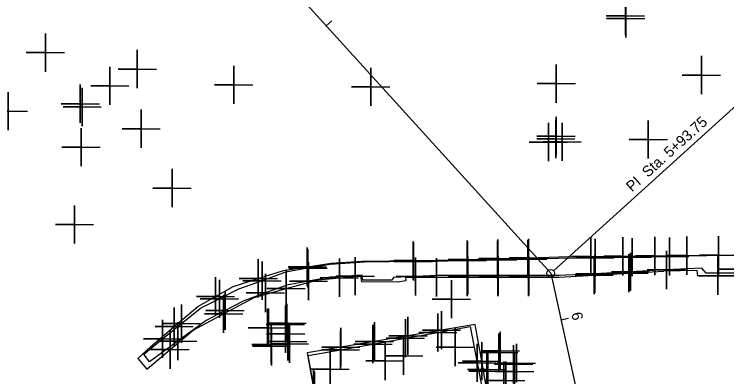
# Model space of a CAD drawing. Extents: x 2260968 to 2264340, y 653057 to 655850.
# Drawn here: x 2261593.4 to 2261686.7, y 655174 to 655221.5 of the extents above; entities that cross this region are included whole.
import ezdxf

# ---------------------------------------------------------------- set-up
doc = ezdxf.new("R2010")
doc.units = 0
for name, color, linetype in [('CL_X_Construction', 7, 'Continuous'), ('Default', 7, 'Continuous'), ('GE_X_CL_10', 7, 'Continuous')]:
    doc.layers.add(name, color=color, linetype=linetype)

msp = doc.modelspace()

# ---------------------------------------------------------------- linework, layer by layer
at = {"layer": 'CL_X_Construction'}
for p, q in [((2261565.655, 655295.67), (2261663.661, 655187.525)), ((2261565.655, 655295.67), (2261663.661, 655187.525)), ((2261663.661, 655187.525), (2261687.579, 655078.757)), ((2261663.661, 655187.525), (2261687.579, 655078.757))]:
    msp.add_line(p, q, dxfattribs=at)
at = {"layer": 'Default'}
for points in [[(2261673.434, 655221.244), (2261673.434, 655223.744), (2261673.434, 655221.244), (2261670.934, 655221.244), (2261673.434, 655221.244), (2261673.434, 655218.744), (2261673.434, 655221.244), (2261675.934, 655221.244)], [(2261673.483, 655220.911), (2261673.483, 655223.411), (2261673.483, 655220.911), (2261670.983, 655220.911), (2261673.483, 655220.911), (2261673.483, 655218.411), (2261673.483, 655220.911), (2261675.983, 655220.911)], [(2261597.529, 655216.43), (2261597.529, 655218.93), (2261597.529, 655216.43), (2261595.029, 655216.43), (2261597.529, 655216.43), (2261597.529, 655213.93), (2261597.529, 655216.43), (2261600.029, 655216.43)], [(2261609.557, 655214.277), (2261609.557, 655216.777), (2261609.557, 655214.277), (2261607.057, 655214.277), (2261609.557, 655214.277), (2261609.557, 655211.777), (2261609.557, 655214.277), (2261612.057, 655214.277)], [(2261683.387, 655213.501), (2261683.387, 655216.001), (2261683.387, 655213.501), (2261680.887, 655213.501), (2261683.387, 655213.501), (2261683.387, 655211.001), (2261683.387, 655213.501), (2261685.887, 655213.501)], [(2261605.963, 655212.074), (2261605.963, 655214.574), (2261605.963, 655212.074), (2261603.463, 655212.074), (2261605.963, 655212.074), (2261605.963, 655209.574), (2261605.963, 655212.074), (2261608.463, 655212.074)], [(2261622.179, 655212.221), (2261622.179, 655214.721), (2261622.179, 655212.221), (2261619.679, 655212.221), (2261622.179, 655212.221), (2261622.179, 655209.721), (2261622.179, 655212.221), (2261624.679, 655212.221)], [(2261664.389, 655212.376), (2261664.389, 655214.876), (2261664.389, 655212.376), (2261661.889, 655212.376), (2261664.389, 655212.376), (2261664.389, 655209.876), (2261664.389, 655212.376), (2261666.889, 655212.376)], [(2261640.108, 655211.946), (2261640.108, 655214.446), (2261640.108, 655211.946), (2261637.608, 655211.946), (2261640.108, 655211.946), (2261640.108, 655209.446), (2261640.108, 655211.946), (2261642.608, 655211.946)], [(2261602.088, 655209.738), (2261602.088, 655212.238), (2261602.088, 655209.738), (2261599.588, 655209.738), (2261602.088, 655209.738), (2261602.088, 655207.238), (2261602.088, 655209.738), (2261604.588, 655209.738)], [(2261602.333, 655209.312), (2261602.333, 655211.812), (2261602.333, 655209.312), (2261599.833, 655209.312), (2261602.333, 655209.312), (2261602.333, 655206.812), (2261602.333, 655209.312), (2261604.833, 655209.312)], [(2261592.675, 655208.766), (2261592.675, 655211.266), (2261592.675, 655208.766), (2261590.175, 655208.766), (2261592.675, 655208.766), (2261592.675, 655206.266), (2261592.675, 655208.766), (2261595.175, 655208.766)], [(2261610.056, 655206.469), (2261610.056, 655208.969), (2261610.056, 655206.469), (2261607.556, 655206.469), (2261610.056, 655206.469), (2261610.056, 655203.969), (2261610.056, 655206.469), (2261612.556, 655206.469)], [(2261664.358, 655205.503), (2261664.358, 655208.003), (2261664.358, 655205.503), (2261661.858, 655205.503), (2261664.358, 655205.503), (2261664.358, 655203.003), (2261664.358, 655205.503), (2261666.858, 655205.503)], [(2261663.363, 655204.716), (2261663.363, 655207.216), (2261663.363, 655204.716), (2261660.863, 655204.716), (2261663.363, 655204.716), (2261663.363, 655202.216), (2261663.363, 655204.716), (2261665.863, 655204.716)], [(2261664.338, 655205.126), (2261664.338, 655207.626), (2261664.338, 655205.126), (2261661.838, 655205.126), (2261664.338, 655205.126), (2261664.338, 655202.626), (2261664.338, 655205.126), (2261666.838, 655205.126)], [(2261665.162, 655204.747), (2261665.162, 655207.247), (2261665.162, 655204.747), (2261662.662, 655204.747), (2261665.162, 655204.747), (2261665.162, 655202.247), (2261665.162, 655204.747), (2261667.662, 655204.747)], [(2261676.44, 655205.057), (2261676.44, 655207.557), (2261676.44, 655205.057), (2261673.94, 655205.057), (2261676.44, 655205.057), (2261676.44, 655202.557), (2261676.44, 655205.057), (2261678.94, 655205.057)], [(2261602.198, 655204.043), (2261602.198, 655206.543), (2261602.198, 655204.043), (2261599.698, 655204.043), (2261602.198, 655204.043), (2261602.198, 655201.543), (2261602.198, 655204.043), (2261604.698, 655204.043)], [(2261614.106, 655198.689), (2261614.106, 655201.189), (2261614.106, 655198.689), (2261611.606, 655198.689), (2261614.106, 655198.689), (2261614.106, 655196.189), (2261614.106, 655198.689), (2261616.606, 655198.689)], [(2261601.329, 655193.918), (2261601.329, 655196.418), (2261601.329, 655193.918), (2261598.829, 655193.918), (2261601.329, 655193.918), (2261601.329, 655191.418), (2261601.329, 655193.918), (2261603.829, 655193.918)], [(2261668.926, 655189.7), (2261668.926, 655192.2), (2261668.926, 655189.7), (2261666.426, 655189.7), (2261668.926, 655189.7), (2261668.926, 655187.2), (2261668.926, 655189.7), (2261671.426, 655189.7)], [(2261673.105, 655189.744), (2261673.105, 655192.244), (2261673.105, 655189.744), (2261670.605, 655189.744), (2261673.105, 655189.744), (2261673.105, 655187.244), (2261673.105, 655189.744), (2261675.605, 655189.744)], [(2261677.283, 655189.788), (2261677.283, 655192.288), (2261677.283, 655189.788), (2261674.783, 655189.788), (2261677.283, 655189.788), (2261677.283, 655187.288), (2261677.283, 655189.788), (2261679.783, 655189.788)], [(2261679.222, 655189.716), (2261679.222, 655192.216), (2261679.222, 655189.716), (2261676.722, 655189.716), (2261679.222, 655189.716), (2261679.222, 655187.216), (2261679.222, 655189.716), (2261681.722, 655189.716)], [(2261681.461, 655189.831), (2261681.461, 655192.331), (2261681.461, 655189.831), (2261678.961, 655189.831), (2261681.461, 655189.831), (2261681.461, 655187.331), (2261681.461, 655189.831), (2261683.961, 655189.831)], [(2261685.64, 655189.875), (2261685.64, 655192.375), (2261685.64, 655189.875), (2261683.14, 655189.875), (2261685.64, 655189.875), (2261685.64, 655187.375), (2261685.64, 655189.875), (2261688.14, 655189.875)], [(2261645.644, 655189.185), (2261645.644, 655191.685), (2261645.644, 655189.185), (2261643.144, 655189.185), (2261645.644, 655189.185), (2261645.644, 655186.685), (2261645.644, 655189.185), (2261648.144, 655189.185)], [(2261645.686, 655189.061), (2261645.686, 655191.561), (2261645.686, 655189.061), (2261643.186, 655189.061), (2261645.686, 655189.061), (2261645.686, 655186.561), (2261645.686, 655189.061), (2261648.186, 655189.061)], [(2261652.739, 655189.331), (2261652.739, 655191.831), (2261652.739, 655189.331), (2261650.239, 655189.331), (2261652.739, 655189.331), (2261652.739, 655186.831), (2261652.739, 655189.331), (2261655.239, 655189.331)], [(2261652.773, 655189.182), (2261652.773, 655191.682), (2261652.773, 655189.182), (2261650.273, 655189.182), (2261652.773, 655189.182), (2261652.773, 655186.682), (2261652.773, 655189.182), (2261655.273, 655189.182)], [(2261656.713, 655189.275), (2261656.713, 655191.775), (2261656.713, 655189.275), (2261654.213, 655189.275), (2261656.713, 655189.275), (2261656.713, 655186.775), (2261656.713, 655189.275), (2261659.213, 655189.275)], [(2261656.742, 655189.439), (2261656.742, 655191.939), (2261656.742, 655189.439), (2261654.242, 655189.439), (2261656.742, 655189.439), (2261656.742, 655186.939), (2261656.742, 655189.439), (2261659.242, 655189.439)], [(2261660.653, 655189.369), (2261660.653, 655191.869), (2261660.653, 655189.369), (2261658.153, 655189.369), (2261660.653, 655189.369), (2261660.653, 655186.869), (2261660.653, 655189.369), (2261663.153, 655189.369)], [(2261660.745, 655189.548), (2261660.745, 655192.048), (2261660.745, 655189.548), (2261658.245, 655189.548), (2261660.745, 655189.548), (2261660.745, 655187.048), (2261660.745, 655189.548), (2261663.245, 655189.548)], [(2261669.469, 655189.547), (2261669.469, 655192.047), (2261669.469, 655189.547), (2261666.969, 655189.547), (2261669.469, 655189.547), (2261669.469, 655187.047), (2261669.469, 655189.547), (2261671.969, 655189.547)], [(2261674.345, 655189.632), (2261674.345, 655192.132), (2261674.345, 655189.632), (2261671.845, 655189.632), (2261674.345, 655189.632), (2261674.345, 655187.132), (2261674.345, 655189.632), (2261676.845, 655189.632)], [(2261631.802, 655188.381), (2261631.802, 655190.881), (2261631.802, 655188.381), (2261629.302, 655188.381), (2261631.802, 655188.381), (2261631.802, 655185.881), (2261631.802, 655188.381), (2261634.302, 655188.381)], [(2261631.887, 655188.175), (2261631.887, 655190.675), (2261631.887, 655188.175), (2261629.387, 655188.175), (2261631.887, 655188.175), (2261631.887, 655185.675), (2261631.887, 655188.175), (2261634.387, 655188.175)], [(2261678.798, 655187.959), (2261678.798, 655190.459), (2261678.798, 655187.959), (2261676.298, 655187.959), (2261678.798, 655187.959), (2261678.798, 655185.459), (2261678.798, 655187.959), (2261681.298, 655187.959)], [(2261688.26, 655188.069), (2261688.26, 655190.569), (2261688.26, 655188.069), (2261685.76, 655188.069), (2261688.26, 655188.069), (2261688.26, 655185.569), (2261688.26, 655188.069), (2261690.76, 655188.069)], [(2261609.619, 655176.346), (2261611.283, 655177.878), (2261614.381, 655180.531), (2261617.479, 655183.184), (2261619.785, 655184.492), (2261622.092, 655185.8), (2261625.388, 655186.851), (2261628.684, 655187.903), (2261631.802, 655188.381), (2261634.921, 655188.86), (2261638.923, 655189.109), (2261642.551, 655189.148), (2261645.644, 655189.185), (2261648.737, 655189.222), (2261652.739, 655189.331), (2261656.742, 655189.439), (2261660.745, 655189.548), (2261664.748, 655189.657), (2261668.926, 655189.7), (2261673.105, 655189.744), (2261677.283, 655189.788), (2261681.461, 655189.831), (2261685.64, 655189.875), (2261689.818, 655189.918)], [(2261687.957, 655189.833), (2261684.098, 655189.801), (2261679.222, 655189.716), (2261674.345, 655189.632), (2261669.469, 655189.547), (2261664.593, 655189.462), (2261660.653, 655189.369), (2261656.713, 655189.275), (2261652.773, 655189.182), (2261648.833, 655189.088), (2261645.686, 655189.061), (2261642.54, 655189.034), (2261639.282, 655188.971), (2261634.815, 655188.663), (2261631.887, 655188.175), (2261628.958, 655187.687), (2261625.884, 655186.555), (2261622.811, 655185.423), (2261620.303, 655184.174), (2261617.796, 655182.925)], [(2261625.388, 655186.851), (2261625.388, 655189.351), (2261625.388, 655186.851), (2261622.888, 655186.851), (2261625.388, 655186.851), (2261625.388, 655184.351), (2261625.388, 655186.851), (2261627.888, 655186.851)], [(2261636.003, 655186.946), (2261636.003, 655189.446), (2261636.003, 655186.946), (2261633.503, 655186.946), (2261636.003, 655186.946), (2261636.003, 655184.446), (2261636.003, 655186.946), (2261638.503, 655186.946)], [(2261638.088, 655187.144), (2261638.088, 655189.644), (2261638.088, 655187.144), (2261635.588, 655187.144), (2261638.088, 655187.144), (2261638.088, 655184.644), (2261638.088, 655187.144), (2261640.588, 655187.144)], [(2261645.95, 655187.108), (2261645.95, 655189.608), (2261645.95, 655187.108), (2261643.45, 655187.108), (2261645.95, 655187.108), (2261645.95, 655184.608), (2261645.95, 655187.108), (2261648.45, 655187.108)], [(2261648.702, 655186.998), (2261648.702, 655189.498), (2261648.702, 655186.998), (2261646.202, 655186.998), (2261648.702, 655186.998), (2261648.702, 655184.498), (2261648.702, 655186.998), (2261651.202, 655186.998)], [(2261652.722, 655187.004), (2261652.722, 655189.504), (2261652.722, 655187.004), (2261650.222, 655187.004), (2261652.722, 655187.004), (2261652.722, 655184.504), (2261652.722, 655187.004), (2261655.222, 655187.004)], [(2261652.812, 655187.228), (2261652.812, 655189.728), (2261652.812, 655187.228), (2261650.312, 655187.228), (2261652.812, 655187.228), (2261652.812, 655184.728), (2261652.812, 655187.228), (2261655.312, 655187.228)], [(2261656.743, 655187.009), (2261656.743, 655189.509), (2261656.743, 655187.009), (2261654.243, 655187.009), (2261656.743, 655187.009), (2261656.743, 655184.509), (2261656.743, 655187.009), (2261659.243, 655187.009)], [(2261656.806, 655187.222), (2261656.806, 655189.722), (2261656.806, 655187.222), (2261654.306, 655187.222), (2261656.806, 655187.222), (2261656.806, 655184.722), (2261656.806, 655187.222), (2261659.306, 655187.222)], [(2261660.763, 655187.015), (2261660.763, 655189.515), (2261660.763, 655187.015), (2261658.263, 655187.015), (2261660.763, 655187.015), (2261660.763, 655184.515), (2261660.763, 655187.015), (2261663.263, 655187.015)], [(2261660.799, 655187.217), (2261660.799, 655189.717), (2261660.799, 655187.217), (2261658.299, 655187.217), (2261660.799, 655187.217), (2261660.799, 655184.717), (2261660.799, 655187.217), (2261663.299, 655187.217)], [(2261669.346, 655187.277), (2261669.346, 655189.777), (2261669.346, 655187.277), (2261666.846, 655187.277), (2261669.346, 655187.277), (2261669.346, 655184.777), (2261669.346, 655187.277), (2261671.846, 655187.277)], [(2261669.461, 655187.461), (2261669.461, 655189.961), (2261669.461, 655187.461), (2261666.961, 655187.461), (2261669.461, 655187.461), (2261669.461, 655184.961), (2261669.461, 655187.461), (2261671.961, 655187.461)], [(2261673.908, 655187.534), (2261673.908, 655190.034), (2261673.908, 655187.534), (2261671.408, 655187.534), (2261673.908, 655187.534), (2261673.908, 655185.034), (2261673.908, 655187.534), (2261676.408, 655187.534)], [(2261674.129, 655187.71), (2261674.129, 655190.21), (2261674.129, 655187.71), (2261671.629, 655187.71), (2261674.129, 655187.71), (2261674.129, 655185.21), (2261674.129, 655187.71), (2261676.629, 655187.71)], [(2261685.536, 655187.2), (2261685.536, 655189.7), (2261685.536, 655187.2), (2261683.036, 655187.2), (2261685.536, 655187.2), (2261685.536, 655184.7), (2261685.536, 655187.2), (2261688.036, 655187.2)], [(2261625.884, 655186.555), (2261625.884, 655189.055), (2261625.884, 655186.555), (2261623.384, 655186.555), (2261625.884, 655186.555), (2261625.884, 655184.055), (2261625.884, 655186.555), (2261628.384, 655186.555)], [(2261631.96, 655186.482), (2261631.96, 655188.982), (2261631.96, 655186.482), (2261629.46, 655186.482), (2261631.96, 655186.482), (2261631.96, 655183.982), (2261631.96, 655186.482), (2261634.46, 655186.482)], [(2261688.158, 655187.542), (2261684.03, 655187.534), (2261683.466, 655188.208), (2261678.798, 655187.959), (2261674.129, 655187.71), (2261669.461, 655187.461), (2261664.792, 655187.212), (2261660.799, 655187.217), (2261656.806, 655187.222), (2261652.812, 655187.228), (2261648.819, 655187.233), (2261645.95, 655187.108), (2261643.081, 655186.983), (2261642.883, 655186.633), (2261639.077, 655186.633), (2261638.978, 655187.284), (2261634.777, 655187.013), (2261631.96, 655186.482), (2261629.144, 655185.951), (2261626.324, 655184.943), (2261623.504, 655183.934), (2261621.046, 655182.629), (2261618.588, 655181.324), (2261614.864, 655178.633), (2261611.139, 655175.942), (2261610.412, 655176.922)], [(2261629.03, 655185.519), (2261629.03, 655188.019), (2261629.03, 655185.519), (2261626.53, 655185.519), (2261629.03, 655185.519), (2261629.03, 655183.019), (2261629.03, 655185.519), (2261631.53, 655185.519)], [(2261644.681, 655186.993), (2261648.702, 655186.998), (2261652.722, 655187.004), (2261656.743, 655187.009), (2261660.763, 655187.015), (2261664.783, 655187.021), (2261669.346, 655187.277), (2261673.908, 655187.534), (2261678.471, 655187.79)], [(2261716.349, 655177.103), (2261713.138, 655179.635), (2261710.462, 655181.474), (2261707.787, 655183.313), (2261705.364, 655184.429), (2261702.941, 655185.545), (2261699.304, 655186.507), (2261695.667, 655187.469), (2261691.94, 655187.71), (2261688.213, 655187.952), (2261688.134, 655187.191), (2261685.536, 655187.2), (2261682.938, 655187.208), (2261682.838, 655187.882), (2261678.471, 655187.79)], [(2261610.798, 655174.98), (2261613.841, 655177.523), (2261616.884, 655180.066), (2261620.859, 655182.21), (2261624.833, 655184.354), (2261629.03, 655185.519), (2261633.226, 655186.685), (2261636.003, 655186.946), (2261638.779, 655187.208), (2261638.882, 655186.456), (2261643.556, 655186.403), (2261644.733, 655186.566), (2261644.681, 655186.993)], [(2261619.785, 655184.492), (2261619.785, 655186.992), (2261619.785, 655184.492), (2261617.285, 655184.492), (2261619.785, 655184.492), (2261619.785, 655181.992), (2261619.785, 655184.492), (2261622.285, 655184.492)], [(2261620.303, 655184.174), (2261620.303, 655186.674), (2261620.303, 655184.174), (2261617.803, 655184.174), (2261620.303, 655184.174), (2261620.303, 655181.674), (2261620.303, 655184.174), (2261622.803, 655184.174)], [(2261626.324, 655184.943), (2261626.324, 655187.443), (2261626.324, 655184.943), (2261623.824, 655184.943), (2261626.324, 655184.943), (2261626.324, 655182.443), (2261626.324, 655184.943), (2261628.824, 655184.943)], [(2261650.668, 655184.13), (2261650.668, 655186.63), (2261650.668, 655184.13), (2261648.168, 655184.13), (2261650.668, 655184.13), (2261650.668, 655181.63), (2261650.668, 655184.13), (2261653.168, 655184.13)], [(2261620.859, 655182.21), (2261620.859, 655184.71), (2261620.859, 655182.21), (2261618.359, 655182.21), (2261620.859, 655182.21), (2261620.859, 655179.71), (2261620.859, 655182.21), (2261623.359, 655182.21)], [(2261621.046, 655182.629), (2261621.046, 655185.129), (2261621.046, 655182.629), (2261618.546, 655182.629), (2261621.046, 655182.629), (2261621.046, 655180.129), (2261621.046, 655182.629), (2261623.546, 655182.629)], [(2261610.412, 655176.922), (2261612.873, 655178.923), (2261615.335, 655180.924), (2261617.796, 655182.925)], [(2261614.381, 655180.531), (2261614.381, 655183.031), (2261614.381, 655180.531), (2261611.881, 655180.531), (2261614.381, 655180.531), (2261614.381, 655178.031), (2261614.381, 655180.531), (2261616.881, 655180.531)], [(2261615.335, 655180.924), (2261615.335, 655183.424), (2261615.335, 655180.924), (2261612.835, 655180.924), (2261615.335, 655180.924), (2261615.335, 655178.424), (2261615.335, 655180.924), (2261617.835, 655180.924)], [(2261626.575, 655180.377), (2261626.575, 655182.877), (2261626.575, 655180.377), (2261624.075, 655180.377), (2261626.575, 655180.377), (2261626.575, 655177.877), (2261626.575, 655180.377), (2261629.075, 655180.377)], [(2261626.747, 655180.394), (2261626.747, 655182.894), (2261626.747, 655180.394), (2261624.247, 655180.394), (2261626.747, 655180.394), (2261626.747, 655177.894), (2261626.747, 655180.394), (2261629.247, 655180.394)], [(2261628.943, 655180.811), (2261628.943, 655183.311), (2261628.943, 655180.811), (2261626.443, 655180.811), (2261628.943, 655180.811), (2261628.943, 655178.311), (2261628.943, 655180.811), (2261631.443, 655180.811)], [(2261629.141, 655181.005), (2261629.141, 655183.505), (2261629.141, 655181.005), (2261626.641, 655181.005), (2261629.141, 655181.005), (2261629.141, 655178.505), (2261629.141, 655181.005), (2261631.641, 655181.005)], [(2261628.97, 655179.589), (2261628.97, 655182.089), (2261628.97, 655179.589), (2261626.47, 655179.589), (2261628.97, 655179.589), (2261628.97, 655177.089), (2261628.97, 655179.589), (2261631.47, 655179.589)], [(2261648.895, 655179.774), (2261648.895, 655182.274), (2261648.895, 655179.774), (2261646.395, 655179.774), (2261648.895, 655179.774), (2261648.895, 655177.274), (2261648.895, 655179.774), (2261651.395, 655179.774)], [(2261649.376, 655180.075), (2261649.376, 655182.575), (2261649.376, 655180.075), (2261646.876, 655180.075), (2261649.376, 655180.075), (2261649.376, 655177.575), (2261649.376, 655180.075), (2261651.876, 655180.075)], [(2261612.873, 655178.923), (2261612.873, 655181.423), (2261612.873, 655178.923), (2261610.373, 655178.923), (2261612.873, 655178.923), (2261612.873, 655176.423), (2261612.873, 655178.923), (2261615.373, 655178.923)], [(2261614.864, 655178.633), (2261614.864, 655181.133), (2261614.864, 655178.633), (2261612.364, 655178.633), (2261614.864, 655178.633), (2261614.864, 655176.133), (2261614.864, 655178.633), (2261617.364, 655178.633)], [(2261629.252, 655178.583), (2261629.252, 655181.083), (2261629.252, 655178.583), (2261626.752, 655178.583), (2261629.252, 655178.583), (2261629.252, 655176.083), (2261629.252, 655178.583), (2261631.752, 655178.583)], [(2261640.589, 655178.596), (2261640.589, 655181.096), (2261640.589, 655178.596), (2261638.089, 655178.596), (2261640.589, 655178.596), (2261640.589, 655176.096), (2261640.589, 655178.596), (2261643.089, 655178.596)], [(2261644.648, 655179.013), (2261644.648, 655181.513), (2261644.648, 655179.013), (2261642.148, 655179.013), (2261644.648, 655179.013), (2261644.648, 655176.513), (2261644.648, 655179.013), (2261647.148, 655179.013)], [(2261644.983, 655179.336), (2261644.983, 655181.836), (2261644.983, 655179.336), (2261642.483, 655179.336), (2261644.983, 655179.336), (2261644.983, 655176.836), (2261644.983, 655179.336), (2261647.483, 655179.336)], [(2261613.841, 655177.523), (2261613.841, 655180.023), (2261613.841, 655177.523), (2261611.341, 655177.523), (2261613.841, 655177.523), (2261613.841, 655175.023), (2261613.841, 655177.523), (2261616.341, 655177.523)], [(2261627.06, 655178.187), (2261627.06, 655180.687), (2261627.06, 655178.187), (2261624.56, 655178.187), (2261627.06, 655178.187), (2261627.06, 655175.687), (2261627.06, 655178.187), (2261629.56, 655178.187)], [(2261627.117, 655177.962), (2261627.117, 655180.462), (2261627.117, 655177.962), (2261624.617, 655177.962), (2261627.117, 655177.962), (2261627.117, 655175.462), (2261627.117, 655177.962), (2261629.617, 655177.962)], [(2261629.479, 655178.292), (2261629.479, 655180.792), (2261629.479, 655178.292), (2261626.979, 655178.292), (2261629.479, 655178.292), (2261629.479, 655175.792), (2261629.479, 655178.292), (2261631.979, 655178.292)], [(2261655.493, 655171.206), (2261654.631, 655176.011), (2261653.769, 655180.815), (2261649.376, 655180.075), (2261644.983, 655179.336), (2261640.589, 655178.596), (2261636.196, 655177.857), (2261631.803, 655177.118), (2261632.639, 655172.484)], [(2261632.752, 655172.176), (2261631.907, 655176.731), (2261636.154, 655177.492), (2261640.401, 655178.253), (2261644.648, 655179.013), (2261648.895, 655179.774), (2261653.142, 655180.535), (2261654.052, 655175.792), (2261654.963, 655171.05)], [(2261636.196, 655177.857), (2261636.196, 655180.357), (2261636.196, 655177.857), (2261633.696, 655177.857), (2261636.196, 655177.857), (2261636.196, 655175.357), (2261636.196, 655177.857), (2261638.696, 655177.857)], [(2261640.401, 655178.253), (2261640.401, 655180.753), (2261640.401, 655178.253), (2261637.901, 655178.253), (2261640.401, 655178.253), (2261640.401, 655175.753), (2261640.401, 655178.253), (2261642.901, 655178.253)], [(2261651.151, 655177.851), (2261651.151, 655180.351), (2261651.151, 655177.851), (2261648.651, 655177.851), (2261651.151, 655177.851), (2261651.151, 655175.351), (2261651.151, 655177.851), (2261653.651, 655177.851)], [(2261636.154, 655177.492), (2261636.154, 655179.992), (2261636.154, 655177.492), (2261633.654, 655177.492), (2261636.154, 655177.492), (2261636.154, 655174.992), (2261636.154, 655177.492), (2261638.654, 655177.492)], [(2261644.41, 655176.718), (2261644.41, 655179.218), (2261644.41, 655176.718), (2261641.91, 655176.718), (2261644.41, 655176.718), (2261644.41, 655174.218), (2261644.41, 655176.718), (2261646.91, 655176.718)], [(2261656.872, 655177.146), (2261656.872, 655179.646), (2261656.872, 655177.146), (2261654.372, 655177.146), (2261656.872, 655177.146), (2261656.872, 655174.646), (2261656.872, 655177.146), (2261659.372, 655177.146)], [(2261657.061, 655177.357), (2261657.061, 655179.857), (2261657.061, 655177.357), (2261654.561, 655177.357), (2261657.061, 655177.357), (2261657.061, 655174.857), (2261657.061, 655177.357), (2261659.561, 655177.357)], [(2261641.977, 655176.036), (2261641.977, 655178.536), (2261641.977, 655176.036), (2261639.477, 655176.036), (2261641.977, 655176.036), (2261641.977, 655173.536), (2261641.977, 655176.036), (2261644.477, 655176.036)], [(2261654.052, 655175.792), (2261654.052, 655178.292), (2261654.052, 655175.792), (2261651.552, 655175.792), (2261654.052, 655175.792), (2261654.052, 655173.292), (2261654.052, 655175.792), (2261656.552, 655175.792)], [(2261654.631, 655176.011), (2261654.631, 655178.511), (2261654.631, 655176.011), (2261652.131, 655176.011), (2261654.631, 655176.011), (2261654.631, 655173.511), (2261654.631, 655176.011), (2261657.131, 655176.011)], [(2261659.168, 655175.759), (2261659.168, 655178.259), (2261659.168, 655175.759), (2261656.668, 655175.759), (2261659.168, 655175.759), (2261659.168, 655173.259), (2261659.168, 655175.759), (2261661.668, 655175.759)], [(2261634.781, 655174.959), (2261634.781, 655177.459), (2261634.781, 655174.959), (2261632.281, 655174.959), (2261634.781, 655174.959), (2261634.781, 655172.459), (2261634.781, 655174.959), (2261637.281, 655174.959)], [(2261655.283, 655174.902), (2261655.283, 655177.402), (2261655.283, 655174.902), (2261652.783, 655174.902), (2261655.283, 655174.902), (2261655.283, 655172.402), (2261655.283, 655174.902), (2261657.783, 655174.902)], [(2261658.812, 655175.603), (2261658.812, 655178.103), (2261658.812, 655175.603), (2261656.312, 655175.603), (2261658.812, 655175.603), (2261658.812, 655173.103), (2261658.812, 655175.603), (2261661.312, 655175.603)], [(2261609.619, 655176.346), (2261610.798, 655174.98)], [(2261655.444, 655174.713), (2261655.444, 655177.213), (2261655.444, 655174.713), (2261652.944, 655174.713), (2261655.444, 655174.713), (2261655.444, 655172.213), (2261655.444, 655174.713), (2261657.944, 655174.713)], [(2261658.936, 655174.665), (2261658.936, 655177.165), (2261658.936, 655174.665), (2261656.436, 655174.665), (2261658.936, 655174.665), (2261658.936, 655172.165), (2261658.936, 655174.665), (2261661.436, 655174.665)], [(2261657.53, 655173.455), (2261657.53, 655175.955), (2261657.53, 655173.455), (2261655.03, 655173.455), (2261657.53, 655173.455), (2261657.53, 655170.955), (2261657.53, 655173.455), (2261660.03, 655173.455)], [(2261657.784, 655173.468), (2261657.784, 655175.968), (2261657.784, 655173.468), (2261655.284, 655173.468), (2261657.784, 655173.468), (2261657.784, 655170.968), (2261657.784, 655173.468), (2261660.284, 655173.468)], [(2261632.639, 655172.484), (2261632.639, 655174.984), (2261632.639, 655172.484), (2261630.139, 655172.484), (2261632.639, 655172.484), (2261632.639, 655169.984), (2261632.639, 655172.484), (2261635.139, 655172.484)], [(2261632.752, 655172.176), (2261632.752, 655174.676), (2261632.752, 655172.176), (2261630.252, 655172.176), (2261632.752, 655172.176), (2261632.752, 655169.676), (2261632.752, 655172.176), (2261635.252, 655172.176)]]:
    msp.add_lwpolyline(points, dxfattribs=at)
at = {"layer": 'GE_X_CL_10'}
for p, q in [((2261565.655, 655295.67), (2261663.661, 655187.525)), ((2261634.28, 655219.945), (2261635.021, 655220.617)), ((2261634.28, 655219.945), (2261635.021, 655220.617)), ((2261664.031, 655187.86), (2261688.443, 655209.984)), ((2261664.031, 655187.86), (2261688.443, 655209.984)), ((2261663.661, 655187.525), (2261687.579, 655078.757)), ((2261665.002, 655181.424), (2261665.979, 655181.638)), ((2261665.002, 655181.424), (2261665.979, 655181.638))]:
    msp.add_line(p, q, dxfattribs=at)
msp.add_circle((2261663.661, 655187.525), 0.5, dxfattribs=at)
msp.add_circle((2261663.661, 655187.525), 0.5, dxfattribs=at)

# ---------------------------------------------------------------- texts
for s, rotation, p in [('PI  Sta. 5+93.75', 42.18426, (2261674.306, 655198.116)), ('PI  Sta. 5+93.75', 42.18426, (2261674.306, 655198.116)), ('6', 282.40214, (2261666.351, 655182.273)), ('6', 282.40214, (2261666.351, 655182.273))]:
    msp.add_text(s, height=1.4, rotation=rotation, dxfattribs=at).set_placement(p)

doc.saveas('drawing.dxf')
